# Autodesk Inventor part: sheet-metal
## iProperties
Author: Administrator
Created: 2001-01
Part Number: sheet-metal
Material: Aluminum
Document SubType Name: Sheet Metal
Designer: Administrator
Control State: 0
Master: False
Checked Out: False
PropertySet Name: Design Tracking Control
Shininess: 60.0
PropertySet Name: _Private Model Information
Density: 0.0
Volumn: 0.0
Area: 0.0
PropertySet Name: Model Information
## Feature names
1. Hole1
2. Rectangular Pattern1
3. Hole2
4. Corner Chamfer1
5. Plate1
6. Plate2
7. Bend1
8. Plate3
9. Bend2
10. Plate4
11. Bend3
12. Plate5
13. Bend4
14. Plate6
15. Bend5
16. FlatPatternExtrusion1
